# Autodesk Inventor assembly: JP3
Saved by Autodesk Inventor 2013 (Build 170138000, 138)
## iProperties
Created: 2021-02
Part Number: JP3
Document SubType Name: Assembly
Designer: Fede
Author: Fede
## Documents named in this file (2)
- C:\0000 FEDE\16GB\0000 INTERIOR\DE_TMP_BAS\BAS_DTON - demora conexion al energizar\pcb\BOR\turn on\Imported Components\BAS_DTON\JP3.iam
- C:\0000 FEDE\16GB\0000 INTERIOR\DE_TMP_BAS\BAS_DTON - demora conexion al energizar\pcb\BOR\turn on\Imported Components\BAS_DTON\bornera2x1.iam
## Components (1 placed, 1 different names)
1. bornera2x1:1 [sub-assembly]
